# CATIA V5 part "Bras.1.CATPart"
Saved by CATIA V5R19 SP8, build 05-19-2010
Part number: Bras.1
Bounding box of the stored display mesh (mm): x -23 to 19.013, y -77.976 to 18.484, z -29.931 to 16
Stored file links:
  G:\EU_thinkMotion\CFAO_2010\MMS_groupe3\MMS_groupe3\jbonnamy\jbonnamy_cfao\Bras.1.CATPart
  G:\EU_thinkMotion\CFAO_2010\MMS_groupe3\MMS_groupe3\jbonnamy\jbonnamy_cfao\jbonnamy_suspension.arriere.directionnelle.CATProduct
  G:\EU_thinkMotion\CFAO_2010\MMS_groupe3\MMS_groupe3\jbonnamy\jbonnamy_cfao\SKL.bras.1.CATPart
  G:\EU_thinkMotion\CFAO_2010\MMS_groupe3\MMS_groupe3\jbonnamy\jbonnamy_cfao\SKL.general.CATPart
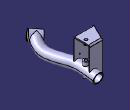
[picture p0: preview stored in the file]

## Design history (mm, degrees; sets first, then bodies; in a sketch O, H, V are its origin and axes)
External parameters (linked from other documents)
  External.Diametre.tube.ext = 14 mm
  External.Diametre.tube.int = 12 mm
  External.Epaisseur.support.10 = 1.5 mm
  External.Rayon.conge.support.10 = 2 mm
  External.Diametre.vis.12 = 3.95 mm
  External.Diametre.fixation.22.24.ext = 7.5 mm
  External.Diametre.fixation.inferieur.24.int = 3.15 mm
  External.Distance.support.10.centre.pignon = 16 mm
  External.Longueur.fixation.24 = 20 mm
  External.Longueur.vis = 28.5 mm
  External.Distance.fixation.24.centre.pignon = 9.5 mm
  `External.Longueur.fixation .22` = 1.5 mm
  External.Largeur.support.10 = 24 mm
  `External.Distance.centre.pivot.plan moteur` = 13.5 mm
  External.Diametre.primitif.roue = 18 mm
  External.Diametre.primitif.vis.sans.fin = 6 mm
  External.Diametre.vis.fixation = 2 mm
  External.Diametre.vis.sans.fin = 6.5 mm
Set1
  Sketch1 "Esquisse.tube.bras.suspension.ext", origin (0.5493, 20.3368, -2.8828), H (-0.9996, 0.027, 0), V (0.0038, 0.1402, 0.9901), geometry linked from another document
  DatumCurve1 "Spline.bras.suspension": linked copy from another document
  Sketch2 "Esquisse.tube.bras.suspension.int", origin (0.5493, 20.3368, -2.8828), H (-0.9996, 0.027, 0), V (0.0038, 0.1402, 0.9901), geometry linked from another document
  Plane1: linked copy from another document
  Point1: linked copy from another document
  Plane2: linked copy from another document
  Point2 "Centre.pignon": linked copy from another document
  Plane3 "Haut.support.10": linked copy from another document
  Line1 "Axe.pivot": linked copy from another document
  Point3 "Point.vis.sans.fin": linked copy from another document
  Plane4: linked copy from another document
Body1 "10" (main body)
  Sketch3 on xy-plane, origin (0, 0, 0), H (1, 0, 0), V (0, 1, 0)
    line L1 (-23, -13.5) -> (5, -13.5)
    line L2 (5, -13.5) -> (5, 10.5)
    line L3 (5, 10.5) -> (-13, 10.5)
    line L4 (-23, -13.5) -> (-23, -11.5)
    line L5 (-23, -11.5) -> (-13, 8.5)
    line L6 (-13, 8.5) -> (-13, 10.5)
    length L3 = 18
    length L1 = 28
    distance L2 V = 5
    length L6 = 2 {= External.Rayon.conge.support.10}
    length L4 = 2 {= External.Rayon.conge.support.10}
    distance L1 L3 = 24 {= External.Largeur.support.10}
    angle L3 L6 = 90
    angle L1 L4 = 90
    distance L1 H = 13.5 {= `External.Distance.centre.pivot.plan moteur`}
  Sketch4 on yz-plane, origin (0, 0, 0), H (0, 1, 0), V (0, 0, 1)
    line L1 (-13.5, -27) -> (-13.5, 14)
    line L2 (-11.5, 16) -> (8.5, 16)
    line L3 (10.5, 14) -> (10.5, -27)
    line L4 (10.5, -27) -> (9, -27)
    line L5 (9, -27) -> (9, 14)
    line L6 (8.5, 14.5) -> (-11.5, 14.5)
    line L7 (-12, 14) -> (-12, -27)
    line L8 (-12, -27) -> (-13.5, -27)
    arc A1 centre (-11.5, 14) radius 2 from (-11.5, 16) to (-13.5, 14) ccw
    point P7 (-11.5, 14)
    arc A2 centre (8.5, 14) radius 2 from (10.5, 14) to (8.5, 16) ccw
    point P10 (8.5, 14)
    arc A3 centre (8.5, 14) radius 0.5 from (9, 14) to (8.5, 14.5) ccw
    point P13 (8.5, 14)
    arc A4 centre (-11.5, 14) radius 0.5 from (-12, 14) to (-11.5, 14.5) cw
    point P16 (-11.5, 14)
    distance L3 L5 = 1.5 {= External.Epaisseur.support.10}
    distance L7 L1 = 1.5 {= External.Epaisseur.support.10}
    distance L6 L2 = 1.5 {= External.Epaisseur.support.10}
    distance L4 L8 = 0
    distance L4 H = 27
    distance L2 H = 16 {= External.Distance.support.10.centre.pignon}
    radius A1 = 2 {= External.Rayon.conge.support.10}
    radius A2 = 2 {= External.Rayon.conge.support.10}
    radius A3 = 0.5 {= External.Rayon.conge.support.10 -External.Epaisseur.support.10}
    radius A4 = 0.5 {= External.Rayon.conge.support.10 -External.Epaisseur.support.10}
    distance P7 L2 = 2 {= External.Rayon.conge.support.10}
    distance P7 L1 = 2 {= External.Rayon.conge.support.10}
    distance P16 P7 = 0
    distance P10 L2 = 2 {= External.Rayon.conge.support.10}
    distance P10 L3 = 2 {= External.Rayon.conge.support.10}
    distance P10 P13 = 0
    distance L3 L1 = 24 {= External.Largeur.support.10}
    distance L1 V = 13.5 {= `External.Distance.centre.pivot.plan moteur`}
  SolidCombine1: FirstComponentProfile Sketch3, FirstComponentDirection Sketch3, SecondComponentProfile Sketch4, SecondComponentDirection Sketch4
  Chamfer1: length 2, second length 2, on edge [face of SolidCombine1 from Sketch4.L4 | face of SolidCombine1 from Sketch3.L6]
  Chamfer2: length 10, second length 10, on edge [face of SolidCombine1 from Sketch3.L4 | face of SolidCombine1 from Sketch4.L8]
  Chamfer3: length 3, second length 3, on edge [face of SolidCombine1 from Sketch3.L2 | face of SolidCombine1 from Sketch4.L4]
  Chamfer4: length 3, second length 3, on edge [face of SolidCombine1 from Sketch4.L8 | face of SolidCombine1 from Sketch3.L2]
  Body2 "2.plein"
    Sweep1: type Unspec, Profile Sketch1, Guide DatumCurve1
    CloseSurface1: CloseElement Sweep1
  Remove1: tool Body2
  Sketch5 on face of SolidCombine1 from Sketch4.L6, origin (0, 8, 14.5), H (0, -1, 0), V (1, 0, 0)
    circle A1 centre (8, 0) radius 3.75
    point P1 (8, 0)
    reference projected point E1 (8, 0) from Point2
    radius A1 = 3.75 {= External.Diametre.fixation.22.24.ext /2}
    distance P1 E1 = 0
  Pad1 "22": profile Sketch5, direction (0, 0, -1), length 1.5 {= `External.Longueur.fixation .22`}
  Sketch6 on face of SolidCombine1 from Sketch4.L2, origin (-10.7686, -2.5674, 16), H (1, 0, 0), V (0, 1, 0)
    point P1 (10.7686, 2.5674)
    reference projected point E1 (10.7686, 2.5674) from Point2
    distance P1 E1 = 0
  Hole1 "26": placed by Sketch6, at (0, 0, 16) direction (0, 0, -1), diameter 3.95 {= External.Diametre.vis.12}, through (limit type 3)
  Sketch7 on Plane4, origin (0, -13.5, 0), H (0, 0, 1), V (1, 0, 0)
    circle A1 centre (0, -12) radius 3.25
    point P1 (0, -12)
    reference projected point E1 (0, -12) from Point3
    circle A2 centre (-9, -21) radius 1
    point P2 (-9, -21)
    circle A3 centre (9, -3) radius 1
    point P3 (9, -3)
    circle A4 centre (9, -21) radius 1
    point P4 (9, -21)
    circle A5 centre (-9, -3) radius 1
    point P5 (-9, -3)
    radius A1 = 3.25 {= External.Diametre.vis.sans.fin /2}
    distance P1 E1 = 0
    radius A2 = 1 {= External.Diametre.vis.fixation /2}
    radius A5 = 1 {= External.Diametre.vis.fixation /2}
    radius A4 = 1 {= External.Diametre.vis.fixation /2}
    radius A3 = 1 {= External.Diametre.vis.fixation /2}
    distance P5 V = 9
    distance P2 V = 9
    distance P4 V = 9
    distance P3 V = 9
    distance P5 H = 3 {= (External.Diametre.primitif.roue +External.Diametre.primitif.vis.sans.fin )/2-9mm}
    distance P2 H = 21 {= (External.Diametre.primitif.roue +External.Diametre.primitif.vis.sans.fin )/2+9mm}
    distance P4 H = 21 {= (External.Diametre.primitif.roue +External.Diametre.primitif.vis.sans.fin )/2+9mm}
    distance P3 H = 3 {= (External.Diametre.primitif.roue +External.Diametre.primitif.vis.sans.fin )/2-9mm}
  Pocket1: profile Sketch7, direction (0, 1, 0), length 1.5 {= External.Epaisseur.support.10}
Body3 "2+4"
  Sweep2 "Balayage.1": type Unspec, Profile Sketch1, Guide DatumCurve1
  Sweep3 "Balayage.2": type Unspec, Profile Sketch2, Guide DatumCurve1
  Blend1 "Surface de raccord.1": StartLimit {blendlimit Curve Sketch1, Support Sweep2}, EndLimit {blendlimit Curve Sketch2, Support Sweep3}
  Blend2 "Surface de raccord.2": StartLimit {blendlimit Curve edge of Sweep2, Point {extremum Reference edge of Sweep2, Direction (1, 2, 3)}, Support Sweep2}, EndLimit {blendlimit Curve edge of Sweep3, Point {extremum Reference edge of Sweep3, Direction (1, 2, 3)}, Support Sweep3}
  Join1 "Assembler.1": Elements (Sweep2; Sweep3; Blend1; Blend2)
  CloseSurface2 "Remplissage.1": CloseElement Join1
  Sketch8 on Plane1, origin (5, -67.5, -10), H (0.758, -0.6323, 0.1598), V (0, -0.245, -0.9695)
    line L1 (8, 7) -> (-8, 7)
    line L2 (-8, 7) -> (-8, 0)
    line L3 (-8, 0) -> (8, 0)
    line L4 (8, 0) -> (8, 7)
    distance L2 L4 = 16
    distance L1 L3 = 7 {= External.Diametre.tube.ext /2}
    distance L3 H = 0
    distance L2 V = 8
  Shaft1 "Révolution.1": profile Sketch8, axis Sketch8.L3, angle 360
  Sketch9 on face of Shaft1 from Sketch8.L4, origin (11.0643, -72.5587, -8.7217), H (0.6522, 0.7349, -0.1857), V (0, 0.245, 0.9695)
    point P1 (0, 0)
    reference projected point E1 (0, 0) from Point1
    distance P1 E1 = 0
  Hole2: placed by Sketch9, at (11.0643, -72.5587, -8.7217) direction (-0.758, 0.6323, -0.1598), diameter 12 {= External.Diametre.tube.int}, through (limit type 3)
  Body4 "24.plein"
    Sketch10 on yz-plane, origin (0, 0, 0), H (0, 1, 0), V (0, 0, 1)
      line L1 (3.75, -9.5) -> (0, -9.5)
      line L2 (0, -9.5) -> (0, -29.5)
      line L3 (0, -29.5) -> (3.75, -29.5)
      line L4 (3.75, -29.5) -> (3.75, -9.5)
      reference projected line E1 (0, -25) -> (0, 25) from Line1
      reference projected line E2 (0, -25) -> (0, 25) from Line1
      distance L1 L3 = 20 {= External.Longueur.fixation.24}
      distance L4 E1 = 3.75 {= External.Diametre.fixation.22.24.ext /2}
      distance L2 E2 = 0
      distance L1 H = 9.5 {= External.Distance.fixation.24.centre.pignon}
    Shaft2: profile Sketch10, axis Line1, angle 360
  Remove2: tool Body4
Body5 "24"
  Sketch11 on yz-plane, origin (0, 0, 0), H (0, 1, 0), V (0, 0, 1)
    line L1 (1.575, -29.5) -> (3.75, -29.5)
    line L2 (3.75, -29.5) -> (3.75, -9.5)
    line L3 (3.75, -9.5) -> (1.975, -9.5)
    line L4 (1.975, -9.5) -> (1.975, -12.5)
    line L5 (1.975, -12.5) -> (1.575, -12.5)
    line L6 (1.575, -12.5) -> (1.575, -29.5)
    reference intersected line E1 through (0, 16) direction (-1, 0) from Plane3
    distance L2 V = 3.75 {= External.Diametre.fixation.22.24.ext /2}
    distance L6 V = 1.575 {= External.Diametre.fixation.inferieur.24.int /2}
    distance L4 V = 1.975 {= External.Diametre.vis.12 /2}
    distance L3 L1 = 20 {= External.Longueur.fixation.24}
    distance E1 L5 = 28.5 {= External.Longueur.vis}
    distance L3 H = 9.5 {= External.Distance.fixation.24.centre.pignon}
  Shaft3: profile Sketch11, axis Line1, angle 360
